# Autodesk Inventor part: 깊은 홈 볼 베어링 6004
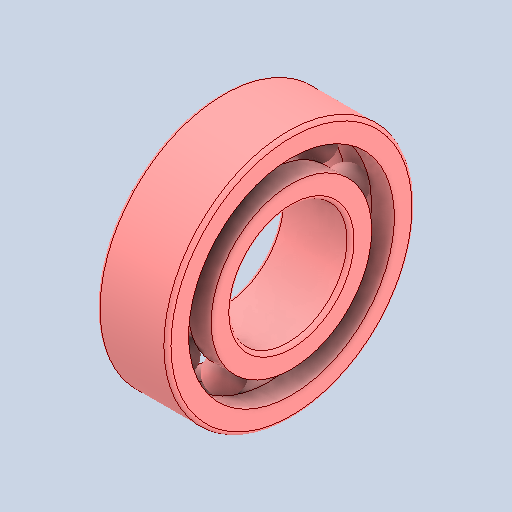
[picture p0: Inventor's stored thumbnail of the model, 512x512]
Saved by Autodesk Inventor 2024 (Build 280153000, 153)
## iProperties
Created: 2025-11
Part Number: 깊은 홈 볼 베어링 6004
Material: 강철, 연강
Description: 깊은 그루브 볼 베어링
Document SubType Name: Modeling
Designer: Eud07
Density: 7.85 g/cm^3
Appearance: 기본값
Author: jhkim
Sending System: Autodesk Inventor 2026
Preprocessor: ST-DEVELOPER v20.1
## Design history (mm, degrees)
node "깊은 홈 볼 베어링 60041"
node "솔리드1"
node "솔리드2"
node "솔리드3"
node "솔리드4"
node "솔리드5"
node "솔리드6"
node "솔리드7"
node "솔리드8"
node "솔리드9"
node "솔리드10"
node "솔리드11"
body "Solid1"
node "Solid1:1"
node "Solid1:2"
node "Solid1:3"
node "Solid1:4"
node "Solid1:5"
node "Solid1:6"
node "Solid1:7"
node "Solid1:8"
node "Solid1:9"
node "Solid1:10"
